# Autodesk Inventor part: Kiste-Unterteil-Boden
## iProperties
Manager: Dr.-Ing. Roland Schröder
Company: www.Das-Entwicklungsbuero.de
Created: 2006-09
Part Number: Kiste-Unterteil-Boden
Project: 12107
Document SubType Name: Modeling
Designer: rsc
Engineer: Dr.-Ing. Roland Schröder
Oberflächen: Ra 6,4
Toleranzen: ISO 2768 - m
Kanten: brechen
Author: rsc
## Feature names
1. Extrusion1
